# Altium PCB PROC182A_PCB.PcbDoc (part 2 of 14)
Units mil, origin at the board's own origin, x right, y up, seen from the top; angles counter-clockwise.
Board outline 3168.31 x 3700.79 mil, 8 copper layers (Top Layer, L2_GND1, L3_SIG1, L4_PWR1, L5_PWR2, L6_SIG2, L7_GND2, Bottom Layer), stack 58.1 mil thick; 580 components, 391 nets, 8314 pads, 4370 vias.
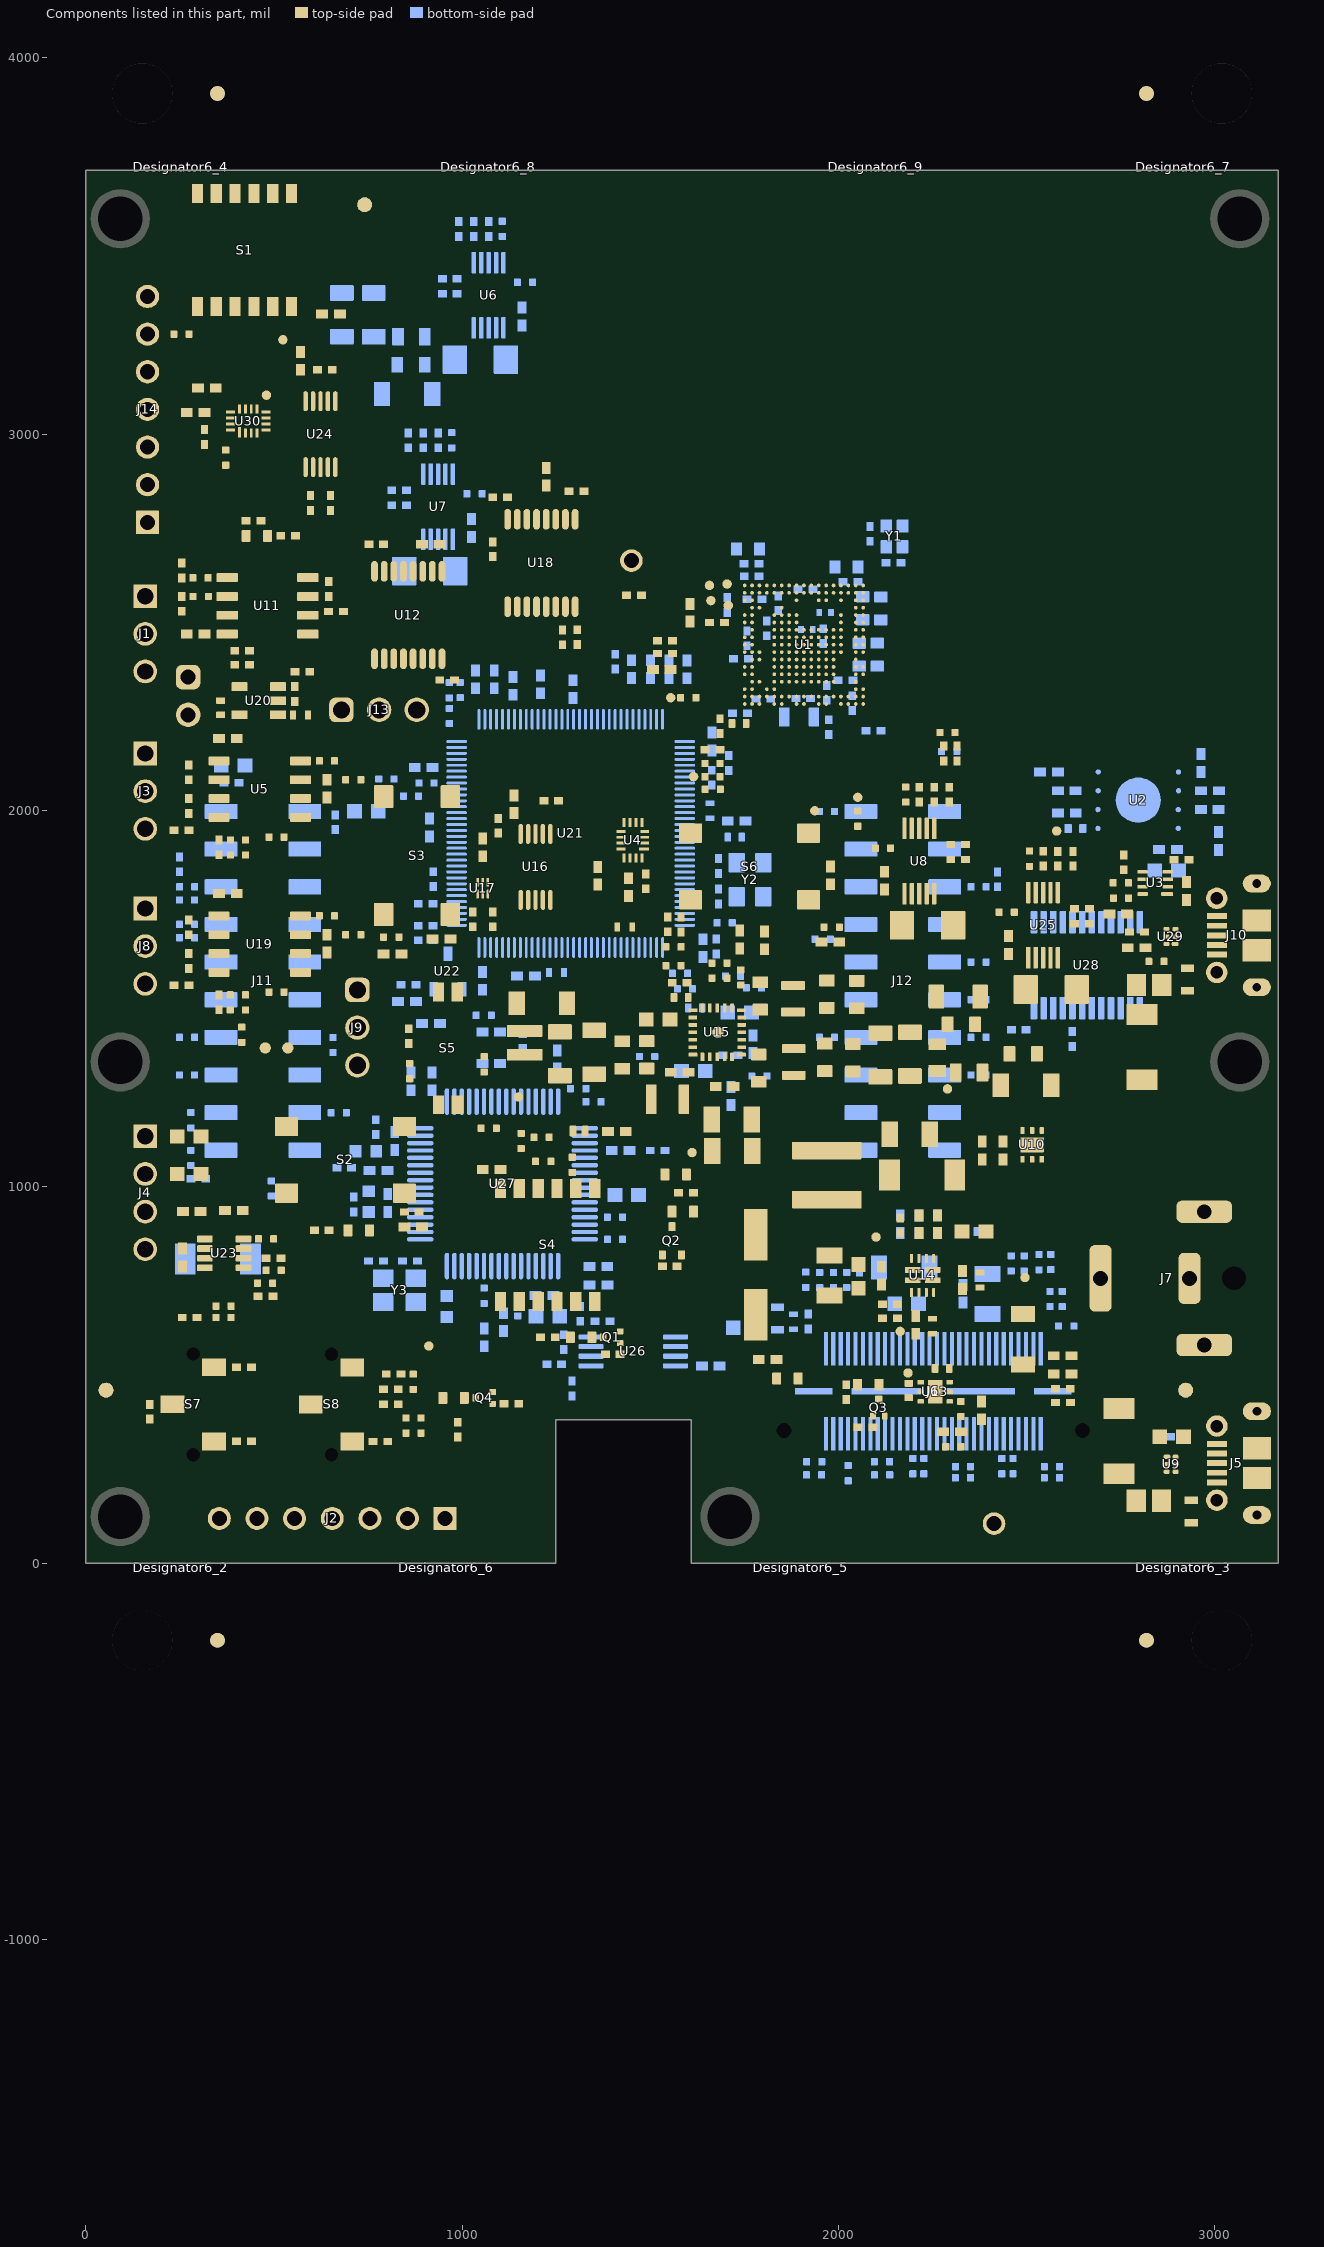
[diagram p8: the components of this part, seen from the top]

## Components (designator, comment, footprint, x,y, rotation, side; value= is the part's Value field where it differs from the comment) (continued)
R206 "CRCW040210K0FKED" 0402L 810.66,462.39 r180 top value=10.0k
R207 "CRCW04027K87FKED" 0402L 818.05,503.14 r0 top value=7.87k
R208 "CRCW040282K5FKED" 0402L 782.82,323.68 r180 top value=82.5k
R209 "CRCW040233R2FKED" 0402 1077.44,1411.22 r0 bottom value=33.2
R210 "ERJ-2GE0R00X" FP-ERJ-2GE0R00X_0402-MFG 269.38,1397.45 r0 bottom value=0
R211 "ERJ-2GE0R00X" FP-ERJ-2GE0R00X_0402-MFG 657,1377.27 r270 bottom value=0
R212 "ERJ-2GE0R00X" FP-ERJ-2GE0R00X_0402-MFG 1969.38,1397.45 r0 bottom value=0
R213 "CRCW0402220RJNED" 0402 945.08,1658.85 r180 top value=220
R214 "ERJ-2GE0R00X" FP-ERJ-2GE0R00X_0402-MFG 811.71,1663.85 r0 top value=0
R215 "CRCW0402100KFKED" 0402 815.16,1618.85 r0 top value=100k
R216 "ERJ-2GE0R00X" FP-ERJ-2GE0R00X_0402-MFG 1308.48,1261.32 r0 bottom value=0
R217 "ERJ-2GE0R00X" FP-ERJ-2GE0R00X_0402-MFG 1348.83,1226.32 r180 bottom value=0
R218 "CRCW040210K0FKED" 0402L 686.9,1050.68 r0 bottom value=10.0k
R219 "ERJ-2GE0R00X" FP-ERJ-2GE0R00X_0402-MFG 2197.61,258.24 r270 bottom value=0
R220 "ERJ-2GE0R00X" FP-ERJ-2GE0R00X_0402-MFG 2226.8,258.24 r270 bottom value=0
R221 "ERJ-2GE0R00X" FP-ERJ-2GE0R00X_0402-MFG 2372.18,1397.45 r0 bottom value=0
R222 "ERJ-2GE0R00X" FP-ERJ-2GE0R00X_0402-MFG 269.38,1297.45 r0 bottom value=0
R223 "ERJ-2GE0R00X" FP-ERJ-2GE0R00X_0402-MFG 2372.18,1297.45 r0 bottom value=0
R224 "ERJ-2GE0R00X" FP-ERJ-2GE0R00X_0402-MFG 279.56,1177.27 r90 bottom value=0
R225 "ERJ-2GE0R00X" FP-ERJ-2GE0R00X_0402-MFG 2330.57,257.17 r180 bottom value=0
R226 "ERJ-2GE0R00X" FP-ERJ-2GE0R00X_0402-MFG 2330.57,227.48 r180 bottom value=0
R227 "ERJ-2GE0R00X" FP-ERJ-2GE0R00X_0402-MFG 2433.83,258.24 r270 bottom value=0
R228 "ERJ-2GE0R00X" FP-ERJ-2GE0R00X_0402-MFG 2463.51,258.24 r270 bottom value=0
R229 "ERJ-2GE0R00X" FP-ERJ-2GE0R00X_0402-MFG 2566.78,227.48 r0 bottom value=0
R230 "ERJ-2GE0R00X" FP-ERJ-2GE0R00X_0402-MFG 2566.78,257.17 r0 bottom value=0
R231 "CRCW040210K0FKED" 0402L 1663.56,2087.29 r90 bottom value=10.0k
R232 "ERJ-2GE0R00X" FP-ERJ-2GE0R00X_0402-MFG 672.18,1197.45 r0 bottom value=0
R233 "ERJ-2RKF1001X" 0402 1054.11,1547.47 r270 bottom value=1.00k
R234 "CRCW04024K87FKED" 0402L 1406.98,2395.63 r270 bottom value=4.87k
R235 "ERJ-2GE0R00X" FP-ERJ-2GE0R00X_0402-MFG 366.12,683.31 r0 top value=0
R236 "CRCW0402330KFKED" 0402L 903.11,1752.47 r180 bottom value=330k
R237 "ERJ-2RKF1001X" 0402 919.5,1280.46 r270 bottom value=1.00k
R238 "ERJ-2GE0R00X" FP-ERJ-2GE0R00X_0402-MFG 279.56,1077.27 r90 bottom value=0
R239 "CRCW0402330KFKED" 0402L 903.11,1655.47 r0 bottom value=330k
R240 "ERJ-2GE0R00X" FP-ERJ-2GE0R00X_0402-MFG 493.41,996.12 r270 bottom value=0
R241 "ERJ-2GE0R00X" FP-ERJ-2GE0R00X_0402-MFG 2325.17,409.98 r90 top value=0
R242 "ERJ-2GE0R00X" FP-ERJ-2GE0R00X_0402-MFG 1058.37,710.97 r270 bottom value=0
R243 "ERJ-2GE0R00X" FP-ERJ-2GE0R00X_0402-MFG 1406.06,919.71 r0 bottom value=0
R244 "ERJ-2GE0R00X" FP-ERJ-2GE0R00X_0402-MFG 870.97,346.19 r0 top value=0
R245 "ERJ-2GE0R00X" FP-ERJ-2GE0R00X_0402-MFG 1561.37,1638.18 r0 top value=0
R246 "CRCW0402100KFKED" 0402L 2092.95,2211.9 r180 bottom value=100k
R247 "CRCW040210K0FKED" 0402L 1685.11,2224.26 r270 top value=10.0k
R248 "CRCW040233R2FKED" 0402 1109.7,641.03 r270 bottom locked value=33.2
R249 "CRCW040233R2FKED" 0402 1058.84,600.34 r270 bottom value=33.2
R250 "CRCW040210K0FKED" 0402L 1539.24,2417.29 r180 top value=10.0k
R251 "CRCW040233R2FKED" 0402 1421.32,1096.88 r0 bottom value=33.2
R252 "ERJ-2GEJ511X" 0402L 1519.6,1096.88 r0 bottom value=510
R253 "CRCW040210K0FKED" 0402L 635.36,3171.01 r180 top value=10.0k
R254 "ERJ-2GE0R00X" FP-ERJ-2GE0R00X_0402-MFG 414.56,1404.55 r90 top value=0
R255 "CRCW0402100KFKED" 0402L 1456.51,2572.49 r0 top value=100k
R256 "CRCW0402100KFKED" 0402L 1081.26,2694.18 r270 top value=100k
R257 "ERJ-2GE0R00X" FP-ERJ-2GE0R00X_0402-MFG 2051.07,1978.47 r90 top value=0
R258 "ERJ-2GEJ511X" 0402L 2020.2,454.73 r270 top value=510
R259 "ERJ-2GE0R00X" FP-ERJ-2GE0R00X_0402-MFG 2844.42,1599.14 r0 top value=0
R260 "CRCW040230K0FKED" 0402L 2792.79,1677.42 r0 top value=30.0k
R261 "CRCW040210K0FKED" 0402L 2279.02,2151.58 r90 top value=10.0k
R262 "CRCW0402220RJNED" 0402 1979.05,1827.93 r270 top value=220
R263 "ERJ-2GEJ511X" 0402L 2071.68,361.35 r180 top value=510
R264 "ERJ-2GE0R00X" FP-ERJ-2GE0R00X_0402-MFG 1981.92,1690.47 r180 top value=0
R265 "CRCW0402100KFKED" 0402 1978.48,1650.47 r180 top value=100k
R267 "ERJ-2GE0R00X" FP-ERJ-2GE0R00X_0402-MFG 1665.13,2090.04 r180 top value=0
R268 "ERJ-2GE0R00X" FP-ERJ-2GE0R00X_0402-MFG 1665.13,2125.04 r180 top value=0
R269 "ERJ-2GE0R00X" FP-ERJ-2GE0R00X_0402-MFG 1600.94,2299.95 r0 top value=0
R270 "ERJ-2GE0R00X" FP-ERJ-2GE0R00X_0402-MFG 1665.95,2056.5 r180 top value=0
R271 "CRCW040210K0FKED" 0402L 315.66,2992.42 r90 top value=10.0k
R272 "RC0402FR-074K7L" 0402 321.95,3122.76 r0 top value=4.70k
R273 "ERJ-2GE0R00X" FP-ERJ-2GE0R00X_0402-MFG 404.36,1921.85 r180 top value=0
R274 "CRCW0402100KFKED" 0402L 597.17,2816.9 r270 top value=100k
R275 "CRCW0402100KFKED" 0402L 650.21,2816.9 r270 top value=100k
R276 "CRCW040210K0FKED" 0402L 2314.66,2151.58 r270 top value=10.0k
R277 "ERJ-2RKF1001X" 0402 651.74,3319.65 r0 top value=1.00k
R278 "ERJ-2GE0R00X" FP-ERJ-2GE0R00X_0402-MFG 1683.76,1554.82 r180 top value=0
R279 "ERJ-2GE0R00X" FP-ERJ-2GE0R00X_0402-MFG 1578.88,1567.54 r180 bottom value=0
R280 "ERJ-2GE0R00X" FP-ERJ-2GE0R00X_0402-MFG 1491.57,1346.5 r180 bottom value=0
R281 "ERJ-2GE0R00X" FP-ERJ-2GE0R00X_0402-MFG 1775.2,1529 r0 bottom value=0
R282 "ERJ-2GE0R00X" FP-ERJ-2GE0R00X_0402-MFG 1789.71,1294.91 r0 bottom value=0
R283 "CRCW040210K0FKED" 0402L 2911.37,1869.68 r180 top value=10.0k
R284 "ERJ-2GE0R00X" FP-ERJ-2GE0R00X_0402-MFG 2293.97,2157 r180 bottom value=0
R285 "ERJ-2GE0R00X" FP-ERJ-2GE0R00X_0402-MFG 371.87,2937.61 r90 top value=0
R286 "ERJ-2GE0R00X" FP-ERJ-2GE0R00X_0402-MFG 254.35,3265.75 r0 top value=0
R287 "ERJ-2GEJ511X" 0402L 627.15,884.63 r180 top value=510
R288 "CRCW040210K0FKED" 0402L 1713.27,1349.74 r180 bottom value=10.0k
R289 "CRCW040219K1FKED" 0402 1773.2,1379.21 r270 bottom value=19.1k
R290 "ERJ-2GE0R00X" FP-ERJ-2GE0R00X_0402-MFG 864.1,2038.44 r0 bottom value=0
S1 "218-6LPST" SW_218-6LPST 421.89,3489.18 r270 top
S2 "PTS645SM43SMTR92 LFS" SW_PTS645SM43SMT 690.06,1072.19 r0 top
S3 "PTS645SM43SMTR92 LFS" SW_PTS645SM43SMT 880.12,1880.34 r270 top
S4 "218-6LPST" SW_218-6LPST 1227.05,846.11 r90 top
S5 "218-2LPST" SW_218-2LP 962.08,1368.36 r270 top
S6 "PTS645SM43SMTR92 LFS" SW_PTS645SM43SMT 1763.78,1851.38 r0 top
S7 "CL-SB-12A-01T" SW_CL-SB-12A-01 285.57,422.47 r180 top
S8 "CL-SB-12A-01T" SW_CL-SB-12A-01 653.02,422.1 r180 top
TP1 "TESTPOINT" TP_25MIL-SMT 911.49,577.38 r270 top
TP2 "TESTPOINT" TP_25MIL-SMT 1936.9,1999.44 r90 top
TP3 "TESTPOINT" TP_25MIL-SMT 2051.07,2035.16 r90 top
TP4 "TESTPOINT" TP_25MIL-SMT 480.15,3103.58 r180 top
TP5 "TESTPOINT" TP_25MIL-SMT 1703.94,2601.77 r90 top
TP6 "TESTPOINT" TP_25MIL-SMT 1657,2598.24 r90 top
TP7 "TESTPOINT" TP_25MIL-SMT 2099.69,866.91 r90 top
TP8 "TESTPOINT" TP_25MIL-SMT 1614.95,2090.04 r90 top
TP9 "TESTPOINT" TP_25MIL-SMT 1554.15,2299.79 r90 top
TP11 "TESTPOINT" TP_25MIL-SMT 1707.08,2545.15 r90 top
TP12 "TESTPOINT" TP_25MIL-SMT 1660.83,2557.74 r90 top
TP13 "TESTPOINT" TP_25MIL-SMT 2163.76,616.28 r90 top
TP14 "TESTPOINT" TP_25MIL-SMT 2495.27,759.44 r90 top
TP15 "TESTPOINT" TP_25MIL-SMT 1610.86,1091.39 r90 top
TP16 "TESTPOINT" TP_25MIL-SMT 1149.56,1239.15 r270 top
TP17 "TESTPOINT" TP_25MIL-SMT 2579.58,1945.65 r90 top
TP18 "TESTPOINT" TP_25MIL-SMT 523.76,3250.69 r90 top
TP19 "TESTPOINT" TP_25MIL-SMT 2289.48,1260.55 r90 top
TP20 "TESTPOINT" TP_25MIL-SMT 2184.58,505.88 r90 top
TP21 "TESTPOINT" TP_VIA_060RND040 2413.15,105.66 r90 top
TP22 "TESTPOINT" TP_VIA_060RND040 1449.62,2663.99 r90 top
U1 "AWRL68442LQGAMF" 0-MFG 1908.07,2440.64 r270 top locked
U2 "MX25V1635FZNQ03" FP-MX25V1635FZNQ03_WSON8-MFG 2796.23,2027.59 r0 bottom
U3 "TMP451AQDQFRQ1" DQF0008A 2841.43,1807.7 r180 top
U4 "TS3A5018RSVR" RSV0016A 1453.74,1921.26 r180 top
U5 "TCAN3403DRQ1" D0008B-MFG 462.45,2056.85 r180 top
U6 "INA228AIDGST" DGS0010A-MFG 1070.46,3368.94 r270 bottom
U7 "INA228AIDGST" DGS0010A-MFG 936.06,2807.15 r270 bottom
U8 "INA228AIDGST" DGS0010A-MFG 2214.6,1865.88 r270 top
U9 "TPD4E004DRYR" DRY0006A 2883.52,263.22 r0 top
U10 "TVS1800DRVR" DRV0006A 2514.32,1111.65 r270 top
U11 "CAT24C08WI-GT3" SOIC-8 482.9,2543.79 r180 top
U12 "TS3A44159PWR" PW0016A_N 856.89,2519.38 r90 top
U13 "TLV75533PDRVR" DRV0006A 2256.79,455.74 r0 top
U14 "TPS2121RUXR" RUX0012A 2223.33,765.07 r180 top
U15 "TPS65036501RAYRQ1" RAY0024B-MFG 1677.79,1410.77 r0 top locked
U16 "TS3A24157DGSR" DGS0010A_N 1194.96,1850.25 r90 top
U17 "SN74LVC1G11DSFR" DSF0006A 1054.8,1793.8 r90 top
U18 "TS3A44159PWR" PW0016A_N 1210.47,2657.7 r90 top
U19 "TCAN3403DRQ1" D0008B-MFG 462.28,1645.14 r180 top
U20 "TPS78417QDBVRQ1" DBV0005A-MFG 459.49,2291.81 r180 top
U21 "TM4C1294NCPDTT3" PDT0128A 1288.51,1939.32 r0 bottom locked
U22 "LM4040C25QDBZR" DBZ0003A_N 962.11,1572.47 r90 bottom
U23 "TLIN1039DDFRQ1" DDF0008A-MFG 367.95,823.53 r180 top
U24 "TS3A24157DGSR" DGS0010A_N 623.69,2999.86 r90 top
U25 "INA228AIDGST" DGS0010A-MFG 2543.46,1695.64 r270 top
U26 "93LC46B-I/ST" TSSOP-8 1454.71,563.12 r0 bottom
U27 "FT4232HL" LQFP64_N 1107.38,1008.3 r0 bottom locked
U28 "TS3A27518EPWR" PW0024A-MFG 2659.93,1589.22 r270 bottom
U29 "TPD4E004DRYR" DRY0006A 2883.23,1665.25 r180 top
U30 "TS3A5018RSVR" RSV0016A 431.86,3034.84 r90 top
Y1 "FW4000044Q" FP-FW4000044Q_4-SMD-2.0x1.6mm-MFG 2148.39,2728.24 r90 bottom
Y2 "ECS-160-8-33Q-RES-TR" FP-ECS-160-8-33Q-RES-TR_SMT4_3MM2_2MM5-MFG 1764.81,1816.36 r270 bottom
Y3 "NX3225SA-12.000M-STD-CRS-2" NDK_NX3225SA 833.8,725.83 r90 bottom
ZZ1 "This Assembly Note is for PCB labels only" AssemblyNoteLabel -334.65,4627.95 r0 top
ZZ2 "These assemblies are ESD sensitive, ESD precautions shall be observed." AssemblyNote -337.73,4557.31 r0 top
ZZ3 "These assemblies must be clean and free from flux and all contaminants. Use of no clean flux is not acceptable." AssemblyNote -336.61,4494.1 r0 top
ZZ4 "These assemblies must comply with workmanship standards IPC-A-610 Class 2, unless otherwise specified." AssemblyNote -336.61,4444.88 r0 top
ZZ5 "INDICATION FOR COMPONENTS D* ARE GIVEN AT THEIR CATHODE SIDE." AssemblyNote -336.61,4382.88 r0 top

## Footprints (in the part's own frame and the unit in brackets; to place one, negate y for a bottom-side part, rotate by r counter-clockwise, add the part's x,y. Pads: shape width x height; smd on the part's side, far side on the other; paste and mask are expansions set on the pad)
0-MFG [mm]
  round 0.25 smd paste+0 mask+0.05: A1(-4,4) A2(-3.5,4) A3(-3,4) A4(-2.5,4) A5(-2,4) A6(-1.5,4) A7(-1,4) A8(-0.5,4) A9(0,4) A10(0.5,4) A12(1.5,4) A13(2,4) A15(3,4) A16(3.5,4) A17(4,4) B1(-4,3.5) B2(-3.5,3.5) B3(-3,3.5) B4(-2.5,3.5) B5(-2,3.5) B6(-1.5,3.5) B7(-1,3.5) B8(-0.5,3.5) B9(0,3.5) B10(0.5,3.5) B11(1,3.5) B12(1.5,3.5) B13(2,3.5) B14(2.5,3.5) B15(3,3.5) B16(3.5,3.5) B17(4,3.5) C1(-4,3) C2(-3.5,3) C16(3.5,3) C17(4,3) D1(-4,2.5) D2(-3.5,2.5) D3(-3,2.5) D5(-2,2.5) D6(-1.5,2.5) D7(-1,2.5) D8(-0.5,2.5) D9(0,2.5) D10(0.5,2.5) D16(3.5,2.5) D17(4,2.5) E1(-4,2) E2(-3.5,2) E7(-1,2) E8(-0.5,2) E9(0,2) E10(0.5,2) E11(1,2) E12(1.5,2) E13(2,2) E14(2.5,2) E16(3.5,2) F1(-4,1.5) F2(-3.5,1.5) F3(-3,1.5) F7(-1,1.5) F8(-0.5,1.5) F9(0,1.5) F10(0.5,1.5) F11(1,1.5) F12(1.5,1.5) F13(2,1.5) F14(2.5,1.5) F16(3.5,1.5) F17(4,1.5) G1(-4,1) G2(-3.5,1) G3(-3,1) G7(-1,1) G8(-0.5,1) G9(0,1) G10(0.5,1) G11(1,1) G12(1.5,1) G13(2,1) G14(2.5,1) G16(3.5,1) G17(4,1) H1(-4,0.5) H2(-3.5,0.5) H7(-1,0.5) H8(-0.5,0.5) H9(0,0.5) H10(0.5,0.5) H11(1,0.5) H12(1.5,0.5) H13(2,0.5) H14(2.5,0.5) H16(3.5,0.5) J1(-4,0) J2(-3.5,0) J7(-1,0) J8(-0.5,0) J9(0,0) J10(0.5,0) J11(1,0) J12(1.5,0) J13(2,0) J14(2.5,0) J16(3.5,0) J17(4,0) K1(-4,-0.5) K2(-3.5,-0.5) K3(-3,-0.5) K5(-2,-0.5) K6(-1.5,-0.5) K7(-1,-0.5) K8(-0.5,-0.5) K9(0,-0.5) K10(0.5,-0.5) K11(1,-0.5) K12(1.5,-0.5) K13(2,-0.5) K14(2.5,-0.5) K16(3.5,-0.5) K17(4,-0.5) L1(-4,-1) L2(-3.5,-1) L5(-2,-1) L6(-1.5,-1) L7(-1,-1) L8(-0.5,-1) L9(0,-1) L10(0.5,-1) L11(1,-1) L12(1.5,-1) L13(2,-1) L14(2.5,-1) L16(3.5,-1) M1(-4,-1.5) M2(-3.5,-1.5) M4(-2.5,-1.5) M5(-2,-1.5) M6(-1.5,-1.5) M7(-1,-1.5) M8(-0.5,-1.5) M9(0,-1.5) M10(0.5,-1.5) M11(1,-1.5) M12(1.5,-1.5) M13(2,-1.5) M14(2.5,-1.5) M16(3.5,-1.5) M17(4,-1.5) N1(-4,-2) N2(-3.5,-2) N5(-2,-2) N6(-1.5,-2) N7(-1,-2) N8(-0.5,-2) N9(0,-2) N10(0.5,-2) N11(1,-2) N12(1.5,-2) N13(2,-2) N14(2.5,-2) N15(3,-2) N16(3.5,-2) N17(4,-2) P1(-4,-2.5) P2(-3.5,-2.5) P15(3,-2.5) P16(3.5,-2.5) R1(-4,-3) R2(-3.5,-3) R4(-2.5,-3) R10(0.5,-3) R11(1,-3) R14(2.5,-3) R16(3.5,-3) R17(4,-3) T1(-4,-3.5) T2(-3.5,-3.5) T3(-3,-3.5) T4(-2.5,-3.5) T5(-2,-3.5) T6(-1.5,-3.5) T7(-1,-3.5) T8(-0.5,-3.5) T9(0,-3.5) T10(0.5,-3.5) T11(1,-3.5) T12(1.5,-3.5) T13(2,-3.5) T14(2.5,-3.5) T15(3,-3.5) T16(3.5,-3.5) T17(4,-3.5) U1(-4,-4) U2(-3.5,-4) U3(-3,-4) U5(-2,-4) U6(-1.5,-4) U8(-0.5,-4) U9(0,-4) U10(0.5,-4) U12(1.5,-4) U13(2,-4) U15(3,-4) U16(3.5,-4) U17(4,-4)
  silkscreen extent -5.12,-4.55 4.55,4.55, body extent -5.05,-5.05 5.05,5.05, height 0.25
0402 [mm] "0402 from SM-752 data"
  rect 0.8x0.6 smd: 1(-0.6,0) 2(0.6,0)
  silkscreen extent -1.22,-0.52 1.22,0.52, body extent -0.55,-0.3 0.55,0.3, height 0.6
0402_070 [mil] "SMD, 2-Leads, Body 1.2x0.7mm, Height 0.7mm"
  rect 15x24 smd: 1(-20,0) 2(20,0)
  body extent -24,-14 24,14, height 28
0402L [mm] "0402 from SM-752 data"
  rect 0.6x0.5 smd: 1(-0.5,0) 2(0.5,0)
  body extent -0.55,-0.3 0.55,0.3, height 0.6
0603 [mm] "0603 from SM-752 data"
  rect 1x0.95 smd: 1(-0.8,0) 2(0.8,0)
  silkscreen extent -1.52,-0.69 1.52,0.69, body extent -0.87,-0.47 0.87,0.47, height 1
0603L [mm] "0603 from SM-752 data"
  rect 0.8x0.85 smd: 1(-0.7,0) 2(0.7,0)
  silkscreen extent -0.07,-0.33 0.07,0.33, body extent -0.87,-0.47 0.87,0.47, height 1
0603S [mil]
  rect 20x35 smd: 1(-30,0) 2(30,0)
  body extent -34,-19 34,19, height 39
0805 [mm] "0805 from SM-752 data"
  rect 1.3x1.5 smd: 1(-0.85,0) 2(0.85,0)
  silkscreen extent -1.72,-0.97 1.72,0.97, body extent -1.1,-0.72 1.1,0.72, height 1.45
1206_180 [mm] "1206_180"
  rect 1.1x1.6 smd: 1(-1.7,0) 2(1.7,0)
  silkscreen extent -0.9,-1 0.9,1, body extent -1.75,-0.95 1.75,0.95, height 1.8
1206_180L [mm] "1206_180"
  rect 1.1x1.75 smd: 1(-1.35,0) 2(1.35,0)
  silkscreen extent -0.4,-0.77 0.4,0.77, body extent -1.75,-0.95 1.75,0.95, height 1.8
AssemblyNote [mil] "Assembly Note"
AssemblyNoteLabel [mil] "Assembly Note for PCB Labels"
BRAKE_WAY_HOLES1X3_CUST [mm]
  round 0.373 hole 0.5 unplated mask+0.152: ""(-0.838,0.746) ""(0,0.746) ""(0.838,0.746)
CE_Mark_5mm [mil] "Minimum text height for CE Mark"
  silkscreen extent -138,-98 138,98
CONN_105017-0001 [mm] "Molex Micro USB-B"
  rect 0.4x1.35 smd: 1(-1.3,1.35) 2(-0.65,1.35) 3(0,1.35) 4(0.65,1.35) 5(1.3,1.35)
  oval 1.2x1.9 hole 0.6 slot 1.3 at 90 deg: 6(-3.5,-1.35) 9(3.5,-1.35)
  rect 1.5x1.9 smd: 7(-1,-1.35) 8(1,-1.35)
  round 1.45 hole 0.85: 10(2.5,1.35) 11(-2.5,1.35)
  Top Layer region: -3.499,-2.301 -2.299,-2.301 -2.299,-0.401 -3.499,-0.401
  Top Layer region: 3.501,-0.401 2.301,-0.401 2.301,-2.301 3.501,-2.301
  silkscreen extent -4.1,-0.2 4.1,1.4, body extent -4.1,-3.93 4.1,1.5, height 2.72
CUI_PJ-063AH [mm] "DC POWER JACK, R/A, TH"
  rrect50% 1.5x4.5 hole 1 square: 1(-4.5,0)
  rrect50% 1.5x3.45 hole 1 square: 2(1.5,0)
  oval 1.35x1.3 hole 1.6 unplated mask+0.102: ALIGN(4.5,0)
  rrect50% 3.75x1.5 hole 1 square: S1(2.5,-4.5) S2(2.5,4.5)
  body extent -5.5,-5.15 7.5,5.15, height 9
D0008B-MFG [mm]
  rrect17% 1.4x0.6 smd paste+0 mask+0: 1(-2.75,1.905) 2(-2.75,0.635) 3(-2.75,-0.635) 4(-2.75,-1.905) 5(2.75,-1.905) 6(2.75,-0.635) 7(2.75,0.635) 8(2.75,1.905)
  silkscreen extent -4.14,-2.5 1.5,2.5, body extent -3,-2.45 3,2.45, height 1.75
DBV0005A-MFG [mm]
  rrect17% 1.1x0.6 smd paste+0 mask+0: 1(-1.3,0.95) 2(-1.3,0) 3(-1.3,-0.95) 4(1.3,-0.95) 5(1.3,0.95)
  silkscreen extent -1.4,-1.53 0.87,1.86, body extent -1.95,-1.78 1.95,1.78, height 0.25
DBZ0003A_N [mm] "SOT23, 3-Leads, Body 2.9x1.3mm, Pitch 0.95mm, Lead Span 2.4mm, IPC Medium Density"
  rrect17% 1x0.6 smd: 1(-1.2,0.95) 2(-1.2,-0.95) 3(1.2,0)
  silkscreen extent 0.2,-1.5 0.7,1.5, body extent -1.26,-1.46 1.26,1.46, height 0.98
DDF0008A-MFG [mm]
  rrect22% 1.05x0.45 smd paste+0 mask+0: 1(-1.3,0.975) 2(-1.3,0.325) 3(-1.3,-0.325) 4(-1.3,-0.975) 5(1.3,-0.975) 6(1.3,-0.325) 7(1.3,0.325) 8(1.3,0.975)
  silkscreen extent -2.38,-1.47 0.4,1.48, body extent -1.92,-1.72 1.92,1.73, height 0.25
DGS0010A-MFG [mm]
  rrect33% 1.45x0.3 smd paste+0 mask+0: 1(-2.2,1) 2(-2.2,0.5) 3(-2.2,0) 4(-2.2,-0.5) 5(-2.2,-1) 6(2.2,-1) 7(2.2,-0.5) 8(2.2,0) 9(2.2,0.5) 10(2.2,1)
  silkscreen extent -3.41,-1.55 1.05,1.55, body extent -2.45,-1.5 2.45,1.5, height 1.1
DGS0010A_N [mm] "TSSOP, 10-Leads, Body 3x3mm, Pitch 0.5mm, IPC Medium Density"
  oval 1.35x0.3 smd: 1(-2.225,1) 2(-2.225,0.5) 3(-2.225,0) 4(-2.225,-0.5) 5(-2.225,-1) 6(2.225,-1) 7(2.225,-0.5) 8(2.225,0) 9(2.225,0.5) 10(2.225,1)
  silkscreen extent -2.75,-1.55 0.9,1.55, body extent -2.45,-1.5 2.45,1.5, height 0.96
DQF0008A [mm] "SON-8"
  rrect40% 0.8x0.25 smd: 1(-0.8,0.75)
  rrect40% 0.7x0.25 smd: 2(-0.85,0.25) 3(-0.85,-0.25) 4(-0.85,-0.75) 5(0.85,-0.75) 6(0.85,-0.25) 7(0.85,0.25) 8(0.85,0.75)
  silkscreen extent -1.15,-1.17 0.38,1.17, body extent -1.05,-1.05 1.05,1.05, height 0.81
DRV0006A [mm] "SON, 6-Leads, Body 2x2mm, Pitch 0.65mm, Thermal Pad 1.6x1mm, TI Recommended"
  rrect33% 0.45x0.3 smd: 1(-0.975,0.65) 2(-0.975,0) 3(-0.975,-0.65) 4(0.975,-0.65) 5(0.975,0) 6(0.975,0.65)
  rrect14% 1x0.7 on Top Paste: 7(0,0.45) 7(0,-0.45)
  rrect10% 1x1.6 smd paste-0.5: 7(0,0)
  silkscreen extent -1.05,-1.2 1.05,1.2, body extent -1.05,-1.05 1.05,1.05, height 0.81
DRY0006A [mm] "USON-6"
  rrect67% 0.45x0.3 smd paste-0.05 mask-0.05: 1(-0.275,0.5)
  rrect67% 0.4x0.3 smd paste-0.05 mask-0.05: 2(-0.3,0) 3(-0.3,-0.5) 4(0.3,-0.5) 5(0.3,0) 6(0.3,0.5)
  body extent -0.5,-0.72 0.5,0.73, height 0.58
DSF0006A [mm] "TI recommended land pattern"
  rrect59% 0.6x0.17 smd mask+0.045: 1(-0.4,0.35) 2(-0.4,0) 3(-0.4,-0.35) 4(0.4,-0.35) 5(0.4,0) 6(0.4,0.35)
  silkscreen extent -0.6,-0.63 0.6,0.63, body extent -0.5,-0.5 0.5,0.5, height 0.48
FIDUCIAL10-20 [mm]
  round 1 smd mask+0.5: 1(0,0)
  Top Layer keep-out circle w1.178: c0,0 r0.5
FP-0022288072_HDR7-MFG [mm]
  rrect6% 1.57x1.57 hole 1.02 paste-2539.97 mask+0: 1(-7.62,-2.925)
  round 1.57 hole 1.02 paste-2539.97 mask+0: 2(-5.08,-2.925) 3(-2.54,-2.925) 4(0,-2.925) 5(2.54,-2.925) 6(5.08,-2.925) 7(7.62,-2.925)
  silkscreen extent -9.11,-3.05 9.01,1.27, body extent -9.11,-3.81 9.12,7.95, height 0.25
FP-CGA4J3X7S1A106K125AE_0805-MFG [mm]
  rrect13% 0.8x1.05 smd paste+0 mask+0: 1(-0.925,0) 2(0.925,0)
  silkscreen extent -0.15,-0.75 0.15,0.75, body extent -1.2,-0.62 1.2,0.63, height 1.5
FP-ECS-160-8-33Q-RES-TR_SMT4_3MM2_2MM5-MFG [mm]
  rrect9% 1.3x1.1 smd paste+0 mask+0: 1(-1.15,-0.9) 2(1.15,-0.9) 3(1.15,0.9) 4(-1.15,0.9)
  silkscreen extent -1.52,-1.96 0.13,1.3, body extent -1.6,-1.25 1.6,1.25, height 0.8
FP-ERJ-2GE0R00X_0402-MFG [mm]
  rrect21% 0.475x0.5 smd paste+0 mask+0: 1(-0.513,0) 2(0.513,0)
  silkscreen extent -0.53,-0.63 0.53,0.63, body extent -0.5,-0.25 0.5,0.25, height 0.4
FP-FW4000044Q_4-SMD-2.0x1.6mm-MFG [mm]
  rrect13% 0.9x0.8 smd paste+0 mask+0: 1(-0.7,-0.55) 2(0.7,-0.55) 3(0.7,0.55) 4(-0.7,0.55)
  silkscreen extent -1.4,-1.1 1.01,1.13, body extent -1,-0.8 1,0.8, height 0.55
FP-GCJ21BR71C475KA01L_0805-MFG [mm]
  rrect14% 0.7x1.3 smd paste+0 mask+0: 1(-1,0) 2(1,0)
  silkscreen extent -0.28,-0.73 0.28,0.73, body extent -1,-0.63 1,0.63, height 1.45
FP-GCM188D70E226ME36D_0603-MFG [mm]
  rrect13% 0.75x0.9 smd paste+0 mask+0: 1(-0.775,0) 2(0.775,0)
  silkscreen extent -0.03,-0.5 0.03,0.5, body extent -0.8,-0.4 0.8,0.4, height 1
FP-GCM188D70J106ME36D_0603-MFG [mm]
  rrect13% 0.75x0.9 smd paste+0 mask+0: 1(-0.775,0) 2(0.775,0)
  body extent -0.8,-0.4 0.8,0.4, height 1
FP-GRM31CR70J226ME19K_1206-MFG [mm]
  rrect10% 1.05x1.6 smd paste+0 mask+0: 1(-1.475,0) 2(1.475,0)
  silkscreen extent -0.58,-0.9 0.58,0.9, body extent -2.1,-1 2.1,1, height 0.25
FP-GRT155C71A225KE13D_0402-MFG [mm]
  rrect22% 0.45x0.6 smd paste+0 mask+0: 1(-0.475,0) 2(0.475,0)
  silkscreen extent -0.5,-0.7 0.5,-0.7, body extent -0.5,-0.25 0.5,0.25, height 0.7
FP-GRT155R70J105KE01D_0402-MFG [mm]
  rrect25% 0.4x0.5 smd paste+0 mask+0: 1(-0.4,0) 2(0.4,0)
  silkscreen extent -0.53,-0.63 0.53,0.63, body extent -0.5,-0.25 0.5,0.25, height 0.55
"FP-LQM2MPZR10MJHL_0806 (2016)-MFG" [mm]
  rrect13% 0.8x2.4 smd paste-1000 mask-1000: 1(-0.8,0) 2(0.8,0)
  silkscreen extent -1.1,-1.5 1.1,1.5, body extent -1.3,-1.3 1.3,1.3, height 0.25
FP-MPZ2012S300ATD25_0805-MFG [mm]
  rrect13% 0.8x1.2 smd paste+0 mask+0: 1(-0.9,0) 2(0.9,0)
  silkscreen extent -0.13,-0.72 0.13,0.72, body extent -1,-0.63 1,0.63, height 1.05
FP-MX25V1635FZNQ03_WSON8-MFG [mm]
  round 0.36 smd paste+0 mask+0: 1(-2.72,1.905) 2(-2.72,0.635) 3(-2.7,-0.635) 4(-2.7,-1.905) 5(2.72,-1.905) 6(2.72,-0.635) 7(2.7,0.635) 8(2.7,1.905)
  round 3.06 smd paste+0 mask+0: 9(0,0)
  Top Layer region: 3,1.705 2.6,1.705 2.523,1.72 2.459,1.764 2.415,1.828 2.4,1.905 2.4,1.905 2.415,1.982 2.459,2.046 2.523,2.09 2.6,2.105 2.6,2.105 3,2.105
  Top Layer region: 3,0.435 2.6,0.435 2.523,0.45 2.459,0.494 2.415,0.558 2.4,0.635 2.4,0.635 2.415,0.712 2.459,0.776 2.523,0.82 2.6,0.835 2.6,0.835 3,0.835
  Top Layer region: 3,-0.835 2.6,-0.835 2.523,-0.82 2.459,-0.776 2.415,-0.712 2.4,-0.635 2.4,-0.635 2.415,-0.558 2.459,-0.494 2.523,-0.45 2.6,-0.435 2.6,-0.435 3,-0.435
  Top Layer region: 3,-2.105 2.6,-2.105 2.523,-2.09 2.459,-2.046 2.415,-1.982 2.4,-1.905 2.4,-1.905 2.415,-1.828 2.459,-1.764 2.523,-1.72 2.6,-1.705 2.6,-1.705 3,-1.705
  Top Layer region: -3,-1.705 -2.6,-1.705 -2.523,-1.72 -2.459,-1.764 -2.415,-1.828 -2.4,-1.905 -2.4,-1.905 -2.427,-2.005 -2.5,-2.078 -2.6,-2.105 -2.6,-2.105 -3,-2.105
  Top Layer region: -3,-0.435 -2.6,-0.435 -2.523,-0.45 -2.459,-0.494 -2.415,-0.558 -2.4,-0.635 -2.4,-0.635 -2.427,-0.735 -2.5,-0.808 -2.6,-0.835 -2.6,-0.835 -3,-0.835
  Top Layer region: -3,0.835 -2.6,0.835 -2.523,0.82 -2.459,0.776 -2.415,0.712 -2.4,0.635 -2.4,0.635 -2.427,0.535 -2.5,0.462 -2.6,0.435 -2.6,0.435 -3,0.435
  Top Layer region: -3,2.105 -2.6,2.105 -2.523,2.09 -2.459,2.046 -2.415,1.982 -2.4,1.905 -2.4,1.905 -2.427,1.805 -2.5,1.732 -2.6,1.705 -2.6,1.705 -3,1.705
  Top Layer region: 1.7,2 1.7,-2 -1.7,-2 -1.7,1.6 -1.3,2 1.7,2
  silkscreen extent -3.05,-2.55 3.05,3.12, body extent -3,-2.49 3,2.49, height 0.8
FP-RC0402FR-1047K5L_0402-MFG [mm]
  rrect20% 0.5x0.6 smd paste+0 mask+0: 1(-0.5,0) 2(0.5,0)
  silkscreen extent -0.5,-0.52 0.5,0.67, body extent -0.5,-0.25 0.5,0.25, height 0.4
FP-SSM3K35AMFV,L3F_SOT-723-MFG [mm]
  rrect25% 0.45x0.4 smd paste+0 mask+0: 1(-0.575,0.4) 2(-0.575,-0.4)
  rrect22% 0.45x0.5 smd paste+0 mask+0: 3(0.575,0)
  silkscreen extent -0.43,-0.98 0.71,0.72, body extent -0.9,-0.73 0.9,0.73, height 0.25
FP-TFM252012ALVA1R5MTAA_1008-MFG [mm]
  rrect14% 0.7x2 smd paste+0 mask+0: 1(-1.1,0) 2(1.1,0)
  silkscreen extent -0.38,-1.1 0.38,1.1, body extent -1.55,-1.2 1.55,1.2, height 0.25
FP-TLMY1100-GS15_0603-MFG [mm]
  rrect17% 0.6x0.8 smd paste+0 mask+0: 1(-0.725,0) 2(0.725,0)
  silkscreen extent -1.61,-0.45 0.05,0.45, body extent -1.12,-0.55 1.12,0.55, height 0.25
FP-WSL1206R0100FEB_1206-MFG [mm]
  rrect6% 1.65x1.93 smd paste+0 mask+0: 1(-1.725,0) 2(1.725,0)
  silkscreen extent -0.53,-0.93 0.53,0.93, body extent -2.65,-1.06 2.65,1.06, height 0.25
FP-WSL1206R0200FEB_1206-MFG [mm]
  rrect6% 1.65x1.93 smd paste+0 mask+0: 1(-1.725,0) 2(1.725,0)
  silkscreen extent -0.53,-0.93 0.53,0.93, body extent -2.65,-1.06 2.65,1.06, height 0.25
FP-WSL1206R0400FEB_1206-MFG [mm]
  rrect6% 1.65x1.93 smd paste+0 mask+0: 1(-1.725,0) 2(1.725,0)
  silkscreen extent -0.53,-0.93 0.53,0.93, body extent -1.6,-0.8 1.6,0.8, height 0.89
FP-XGL5050-472MEC_SMT2_5MM28_5MM48-MFG [mm]
  rrect8% 1.18x4.7 smd paste+0 mask+0: 1(-1.655,0) 2(1.655,0)
  silkscreen extent -3.4,-2.84 2.74,2.84, body extent -2.84,-2.94 2.84,2.94, height 0.25
IEC_HotSurface_Small [mil]
  silkscreen extent -107,-93 107,92
LQFP64_N [mm] "Thin QFP, 64-Leads, Body 10x10mm, Pitch 0.5mm, IPC Medium Density"
  oval 1.8x0.3 smd: 1(-5.55,3.75) 2(-5.55,3.25) 3(-5.55,2.75) 4(-5.55,2.25) 5(-5.55,1.75) 6(-5.55,1.25) 7(-5.55,0.75) 8(-5.55,0.25) 9(-5.55,-0.25) 10(-5.55,-0.75) 11(-5.55,-1.25) 12(-5.55,-1.75) 13(-5.55,-2.25) 14(-5.55,-2.75) 15(-5.55,-3.25) 16(-5.55,-3.75) 33(5.55,-3.75) 34(5.55,-3.25) 35(5.55,-2.75) 36(5.55,-2.25) 37(5.55,-1.75) 38(5.55,-1.25) 39(5.55,-0.75) 40(5.55,-0.25) 41(5.55,0.25) 42(5.55,0.75) 43(5.55,1.25) 44(5.55,1.75) 45(5.55,2.25) 46(5.55,2.75) 47(5.55,3.25) 48(5.55,3.75)
  oval 0.3x1.8 smd: 17(-3.75,-5.55) 18(-3.25,-5.55) 19(-2.75,-5.55) 20(-2.25,-5.55) 21(-1.75,-5.55) 22(-1.25,-5.55) 23(-0.75,-5.55) 24(-0.25,-5.55) 25(0.25,-5.55) 26(0.75,-5.55) 27(1.25,-5.55) 28(1.75,-5.55) 29(2.25,-5.55) 30(2.75,-5.55) 31(3.25,-5.55) 32(3.75,-5.55) 49(3.75,5.55) 50(3.25,5.55) 51(2.75,5.55) 52(2.25,5.55) 53(1.75,5.55) 54(1.25,5.55) 55(0.75,5.55) 56(0.25,5.55) 57(-0.25,5.55) 58(-0.75,5.55) 59(-1.25,5.55) 60(-1.75,5.55) 61(-2.25,5.55) 62(-2.75,5.55) 63(-3.25,5.55) 64(-3.75,5.55)
  silkscreen extent -6.96,-4.25 4.25,4.25, body extent -5,-5 5,5, height 1.6
NDK_NX3225SA [mm] "NDK"
  rect 1.2x1.4 smd: 1(-0.8,1.1) 2(-0.8,-1.1) 3(0.8,-1.1) 4(0.8,1.1)
  body extent -1.3,-1.65 1.3,1.65, height 0.7
PDT0128A [mm] "Thin QFP, 128-Leads, Body 14x14mm, Pitch 0.4mm"
  oval 1.4x0.2 smd: 1(-7.7,6.2) 2(-7.7,5.8) 3(-7.7,5.4) 4(-7.7,5) 5(-7.7,4.6) 6(-7.7,4.2) 7(-7.7,3.8) 8(-7.7,3.4) 9(-7.7,3) 10(-7.7,2.6) 11(-7.7,2.2) 12(-7.7,1.8) 13(-7.7,1.4) 14(-7.7,1) 15(-7.7,0.6) 16(-7.7,0.2) 17(-7.7,-0.2) 18(-7.7,-0.6) 19(-7.7,-1) 20(-7.7,-1.4) 21(-7.7,-1.8) 22(-7.7,-2.2) 23(-7.7,-2.6) 24(-7.7,-3) 25(-7.7,-3.4) 26(-7.7,-3.8) 27(-7.7,-4.2) 28(-7.7,-4.6) 29(-7.7,-5) 30(-7.7,-5.4) 31(-7.7,-5.8) 32(-7.7,-6.2) 65(7.7,-6.2) 66(7.7,-5.8) 67(7.7,-5.4) 68(7.7,-5) 69(7.7,-4.6) 70(7.7,-4.2) 71(7.7,-3.8) 72(7.7,-3.4) 73(7.7,-3) 74(7.7,-2.6) 75(7.7,-2.2) 76(7.7,-1.8) 77(7.7,-1.4) 78(7.7,-1) 79(7.7,-0.6) 80(7.7,-0.2) 81(7.7,0.2) 82(7.7,0.6) 83(7.7,1) 84(7.7,1.4) 85(7.7,1.8) 86(7.7,2.2) 87(7.7,2.6) 88(7.7,3) 89(7.7,3.4) 90(7.7,3.8) 91(7.7,4.2) 92(7.7,4.6) 93(7.7,5) 94(7.7,5.4) 95(7.7,5.8) 96(7.7,6.2)
  oval 0.2x1.4 smd: 33(-6.2,-7.7) 34(-5.8,-7.7) 35(-5.4,-7.7) 36(-5,-7.7) 37(-4.6,-7.7) 38(-4.2,-7.7) 39(-3.8,-7.7) 40(-3.4,-7.7) 41(-3,-7.7) 42(-2.6,-7.7) 43(-2.2,-7.7) 44(-1.8,-7.7) 45(-1.4,-7.7) 46(-1,-7.7) 47(-0.6,-7.7) 48(-0.2,-7.7) 49(0.2,-7.7) 50(0.6,-7.7) 51(1,-7.7) 52(1.4,-7.7) 53(1.8,-7.7) 54(2.2,-7.7) 55(2.6,-7.7) 56(3,-7.7) 57(3.4,-7.7) 58(3.8,-7.7) 59(4.2,-7.7) 60(4.6,-7.7) 61(5,-7.7) 62(5.4,-7.7) 63(5.8,-7.7) 64(6.2,-7.7) 97(6.2,7.7) 98(5.8,7.7) 99(5.4,7.7) 100(5,7.7) 101(4.6,7.7) 102(4.2,7.7) 103(3.8,7.7) 104(3.4,7.7) 105(3,7.7) 106(2.6,7.7) 107(2.2,7.7) 108(1.8,7.7) 109(1.4,7.7) 110(1,7.7) 111(0.6,7.7) 112(0.2,7.7) 113(-0.2,7.7) 114(-0.6,7.7) 115(-1,7.7) 116(-1.4,7.7) 117(-1.8,7.7) 118(-2.2,7.7) 119(-2.6,7.7) 120(-3,7.7) 121(-3.4,7.7) 122(-3.8,7.7) 123(-4.2,7.7) 124(-4.6,7.7) 125(-5,7.7) 126(-5.4,7.7) 127(-5.8,7.7) 128(-6.2,7.7)
  silkscreen extent -7.7,-6.3 6.3,6.99, body extent -8,-8 8,8, height 1.07
PW0016A_N [mm] "TSOP, 16-Leads, Body 5x4.4mm, Pitch 0.65mm, IPC Medium Density"
  oval 1.4x0.45 smd: 1(-2.95,2.275) 2(-2.95,1.625) 3(-2.95,0.975) 4(-2.95,0.325) 5(-2.95,-0.325) 6(-2.95,-0.975) 7(-2.95,-1.625) 8(-2.95,-2.275) 9(2.95,-2.275) 10(2.95,-1.625) 11(2.95,-0.975) 12(2.95,-0.325) 13(2.95,0.325) 14(2.95,0.975) 15(2.95,1.625) 16(2.95,2.275)
  silkscreen extent -3.5,-2.55 1.85,2.75, body extent -3.21,-2.5 3.21,2.5, height 1
PW0024A-MFG [mm]
  rrect22% 1.5x0.45 smd paste+0 mask+0: 1(-2.9,3.575) 2(-2.9,2.925) 3(-2.9,2.275) 4(-2.9,1.625) 5(-2.9,0.975) 6(-2.9,0.325) 7(-2.9,-0.325) 8(-2.9,-0.975) 9(-2.9,-1.625) 10(-2.9,-2.275) 11(-2.9,-2.925) 12(-2.9,-3.575) 13(2.9,-3.575) 14(2.9,-2.925) 15(2.9,-2.275) 16(2.9,-1.625) 17(2.9,-0.975) 18(2.9,-0.325) 19(2.9,0.325) 20(2.9,0.975) 21(2.9,1.625) 22(2.9,2.275) 23(2.9,2.925) 24(2.9,3.575)
  silkscreen extent -4.37,-3.95 1.78,3.95, body extent -3.2,-3.9 3.2,3.9, height 1.2
RAY0024B-MFG [mm]
  rrect40% 0.625x0.25 smd paste+0 mask+0: 1(-1.637,1.5) 7(-1.637,-1.5) 13(1.637,-1.5) 19(1.637,1.5)
  rrect40% 0.6x0.25 smd paste+0 mask+0: 2(-1.65,1) 3(-1.65,0.5) 4(-1.65,0) 5(-1.65,-0.5) 6(-1.65,-1) 14(1.65,-1) 15(1.65,-0.5) 16(1.65,0) 17(1.65,0.5) 18(1.65,1)
  rrect40% 0.25x0.6 smd paste+0 mask+0: 8(-1,-1.65) 9(-0.5,-1.65) 10(0,-1.65) 11(0.5,-1.65) 12(1,-1.65) 20(1,1.65) 21(0.5,1.65) 22(0,1.65) 23(-0.5,1.65) 24(-1,1.65)
  round 0.777 smd paste-25.4 mask+0: ""(0.037,-0.003)
  Top Layer region: -1.95,0.075 -1.943,0.1 -1.925,0.118 -1.9,0.125 -1.9,0.125 -1.4,0.125 -1.378,0.12 -1.361,0.106 -1.361,0.106 -1.344,0.092 -1.322,0.088 -1.322,0.088 -0.426,0.088 -0.406,0.091 -0.39,0.102 -0.379,0.118 -0.375,0.138 -0.376,0.138 -0.376,0.601 -0.369,0.626 -0.35,0.644 -0.325,0.651 -0.326,0.651 0.456,0.651 0.48,0.644 0.499,0.626 0.505,0.601 0.505,0.601 0.505,0.1 0.509,0.081 0.52,0.065 0.536,0.054 0.556,0.05 0.556,0.05 1.303,0.05 1.324,0.055 1.342,0.068 1.352,0.088 1.352,0.088 1.362,0.107 1.379,0.12 1.4,0.125 1.4,0.125 1.9,0.125 1.925,0.118 1.943,0.1 1.95,0.075 1.95,0.075 1.95,-0.075 1.943,-0.1 1.925,-0.118 1.9,-0.125 1.9,-0.125 0.556,-0.125 0.536,-0.129 0.52,-0.14 0.509,-0.156 0.506,-0.175 0.505,-0.175 0.505,-0.601 0.499,-0.626 0.48,-0.644 0.456,-0.651 0.456,-0.651 -0.326,-0.651 -0.35,-0.644 -0.369,-0.626 -0.375,-0.601 -0.375,-0.601 -0.376,-0.138 -0.379,-0.118 -0.39,-0.102 -0.406,-0.091 -0.425,-0.088 -0.426,-0.087 -1.322,-0.088 -1.344,-0.092 -1.361,-0.106 -1.361,-0.106 -1.378,-0.12 -1.4,-0.125 -1.4,-0.125 -1.9,-0.125 -1.925,-0.118 -1.943,-0.1 -1.95,-0.075 -1.95,-0.075
  silkscreen extent -2.56,1.55 -2.31,1.8, body extent -2.05,-2.05 2.05,2.05, height 0.25
RSV0016A [mm] "QFN, 16-Leads, Body 1.8x2.6mm, Pitch 0.4mm, TI Recommended"
  rect 0.7x0.2 smd: 1(-0.75,0.6)
  rect 0.6x0.2 smd: 2(-0.8,0.2) 3(-0.8,-0.2) 4(-0.8,-0.6) 9(0.8,-0.6) 10(0.8,-0.2) 11(0.8,0.2) 12(0.8,0.6)
  rect 0.2x0.6 smd: 5(-0.6,-1.2) 6(-0.2,-1.2) 7(0.2,-1.2) 8(0.6,-1.2) 13(0.6,1.2) 14(0.2,1.2) 15(-0.2,1.2) 16(-0.6,1.2)
  silkscreen extent -1.08,-1.33 1.08,1.45, body extent -0.92,-1.32 0.92,1.33, height 0.56
RUX0012A [mm] "VQFN-HR-12"
  rrect25% 1.05x0.4 smd: 1(-0.675,0.325) 2(-0.675,-0.375) 7(0.675,-0.375) 8(0.675,0.325)
  rrect40% 0.2x0.6 smd: 3(-0.75,-1.15) 4(-0.25,-1.15) 5(0.25,-1.15) 6(0.75,-1.15) 9(0.75,1.15) 10(0.25,1.15) 11(-0.25,1.15) 12(-0.75,1.15)
  silkscreen extent -1.15,-1.4 1.15,1.35, body extent -1.05,-1.3 1.05,1.3, height 1
Samtec_QSH-030-01-X-D-A [mm] "Receptacle, 0.5 mm, 30x2, TH"
  rect 2.27x0.279 smd: 1(-2.865,7.25) 2(2.865,7.25) 3(-2.865,6.75) 4(2.865,6.75) 5(-2.865,6.25) 6(2.865,6.25) 7(-2.865,5.75) 8(2.865,5.75) 9(-2.865,5.25) 10(2.865,5.25) 11(-2.865,4.75) 12(2.865,4.75) 13(-2.865,4.25) 14(2.865,4.25) 15(-2.865,3.75) 16(2.865,3.75) 17(-2.865,3.25) 18(2.865,3.25) 19(-2.865,2.75) 20(2.865,2.75) 21(-2.865,2.25) 22(2.865,2.25) 23(-2.865,1.75) 24(2.865,1.75) 25(-2.865,1.25) 26(2.865,1.25) 27(-2.865,0.75) 28(2.865,0.75) 29(-2.865,0.25) 30(2.865,0.25) 31(-2.865,-0.25) 32(2.865,-0.25) 33(-2.865,-0.75) 34(2.865,-0.75) 35(-2.865,-1.25) 36(2.865,-1.25) 37(-2.865,-1.75) 38(2.865,-1.75) 39(-2.865,-2.25) 40(2.865,-2.25) 41(-2.865,-2.75) 42(2.865,-2.75) 43(-2.865,-3.25) 44(2.865,-3.25) 45(-2.865,-3.75) 46(2.865,-3.75) 47(-2.865,-4.25) 48(2.865,-4.25) 49(-2.865,-4.75) 50(2.865,-4.75) 51(-2.865,-5.25) 52(2.865,-5.25) 53(-2.865,-5.75) 54(2.865,-5.75) 55(-2.865,-6.25) 56(2.865,-6.25) 57(-2.865,-6.75) 58(2.865,-6.75) 59(-2.865,-7.25) 60(2.865,-7.25)
  round 0 hole 1.02 unplated: MH1(2.67,10.065) MH2(2.67,-10.065)
  rect 0.43x2.54 smd: MP1(0,8.065) MP4(0,-8.065)
  rect 0.43x4.7 smd: MP2(0,3.175) MP3(0,-3.175)
  silkscreen extent -3.85,-10.66 3.62,10.66, body extent -3.75,-10.64 3.75,10.67, height 3.25
Samtec_SSM-110-x-DV [mm] "Receptacle, 2.54mm, 10x2, SMT"
  rrect10% 1.02x2.22 smd: 1(-11.43,2.825) 2(-11.43,-2.825) 3(-8.89,2.825) 4(-8.89,-2.825) 5(-6.35,2.825) 6(-6.35,-2.825) 7(-3.81,2.825) 8(-3.81,-2.825) 9(-1.27,2.825) 10(-1.27,-2.825) 11(1.27,2.825) 12(1.27,-2.825) 13(3.81,2.825) 14(3.81,-2.825) 15(6.35,2.825) 16(6.35,-2.825) 17(8.89,2.825) 18(8.89,-2.825) 19(11.43,2.825) 20(11.43,-2.825)
  silkscreen extent -13.02,-2.54 12.7,2.54, body extent -12.7,-3.52 12.7,3.52, height 7.42
SM_RADIAL_6.3BMM [mm] "Nichicon 6.3x7.7"
  rect 3.5x1.6 smd: 1(-2.7,0) 2(2.7,0)
  silkscreen extent -3.4,-3.4 3.4,3.4, body extent -3.4,-3.4 3.4,3.4, height 8
SOD-128 [mm] "SMD, 2-Leads, Body 4x2.7mm, Height 1.1mm"
  rect 1.4x2.1 smd paste-0.1: 1(-2.2,0) 2(2.2,0)
  silkscreen extent -3.45,-1.45 2.95,1.45, body extent -2.5,-1.35 2.5,1.35, height 1.11
SOD-882 [mm] "Skyworks"
  rrect42% 0.475x0.75 smd mask+0.05: 1(-0.412,0) 2(0.412,0)
  silkscreen extent -1.1,-0.35 -0.87,0.35, body extent -0.5,-0.3 0.5,0.3, height 0.5
SOIC-8 [mm] "duplicate of SO-8.  SOIC, 8-Leads, Body 5.0x4.0mm (max), Pitch 1.27mm, IPC Medium Density"
  rrect17% 1.45x0.6 smd: 1(-2.725,1.905) 2(-2.725,0.635) 3(-2.725,-0.635) 4(-2.725,-1.905) 5(2.725,-1.905) 6(2.725,-0.635) 7(2.725,0.635) 8(2.725,1.905)
  silkscreen extent -3.5,-2.5 0.9,2.5, body extent -3,-2.45 3,2.45, height 1.63
SolderJumper [mil] "Solder Jumper"
  round 30 smd paste-40: 1(-30,0) 2(30,0)
  Top Layer region: -2.5,-50 -24.19,-45.05 -41.59,-31.17 -51.25,-11.13 -51.25,11.13 -41.59,31.17 -24.19,45.05 -2.5,50 -2.5,50
  Top Layer region: 2.5,-50 24.19,-45.05 41.59,-31.17 51.25,-11.13 51.25,11.13 41.59,31.17 24.19,45.05 2.5,50 2.5,50
SOT-323 [mm] "Diodes Inc recommended land pattern.  2016-02-24"
  rrect21% 0.6x0.47 smd: 1(-0.95,0.65) 2(-0.95,-0.65) 3(0.95,0)
  silkscreen extent -1.14,-1.22 0.77,1.22, body extent -1.13,-1.13 1.12,1.12, height 1.13
Sullins_xxC07SAAN [mm] "Header, 2.54 mm, 7x1, TH"
  rect 1.55x1.55 hole 1.016: 1(-7.62,0)
  round 1.55 hole 1.016: 2(-5.08,0) 3(-2.54,0) 4(0,0) 5(2.54,0) 6(5.08,0) 7(7.62,0)
  silkscreen extent -8.89,-1.27 8.89,1.7, body extent -8.89,-1.27 8.89,1.27, height 8.38
SW_218-2LP [mm] "SMD, 4-Leads, Body 3.71x5.8mm, Pitch 1.27mm"
  rect 1.27x0.76 smd: 1(-3.81,0.635) 2(-3.81,-0.635) 3(3.81,-0.635) 4(3.81,0.635)
  silkscreen extent -2.9,-1.86 2.9,2.09, body extent -4.22,-1.86 4.22,1.85, height 2.62
SW_218-6LPST [mm] "SMD, 12-Leads, Body 5.8x8.79mm"
  rect 1.27x0.76 smd: 1(-3.81,3.175) 2(-3.81,1.905) 3(-3.81,0.635) 4(-3.81,-0.635) 5(-3.81,-1.905) 6(-3.81,-3.175) 7(3.81,-3.175) 7(3.81,-3.175) 8(3.81,-1.905) 9(3.81,-0.635) 10(3.81,0.635) 11(3.81,1.905) 12(3.81,3.175)
  silkscreen extent -2.9,-4.4 2.9,4.7, body extent -4.22,-4.4 4.22,4.39, height 2.62
SW_CL-SB-12A-01 [mm] "SMD, 3-Leads, Body 8.5x3.5mm, Pitch 2.5mm"
  rect 1.6x1.2 smd: 1(-1.4,2.5) 2(1.4,0) 3(-1.4,-2.5)
  round 0 hole 0.9 unplated: MH1(0,3.4) MH2(0,-3.4)
  silkscreen extent -2.71,-4.25 1.75,4.25, body extent -1.75,-4.25 1.75,4.25, height 5.5
SW_PTS645SM43SMT [mm] "SMD, 4-Leads, Body 6x6mm"
  rrect8% 1.55x1.3 smd: 1(-3.975,2.25) 2(3.975,2.25) 3(-3.975,-2.25) 4(3.975,-2.25)
  body extent -4.5,-3 4.5,3, height 4.3
TFM201610ALMA [mm] "TDK"
  rrect17% 0.6x1.6 smd: 1(-0.9,0) 2(0.9,0)
  body extent -1.1,-0.9 1.1,0.9, height 1
TP_25MIL-SMT [mil]
  round 25 smd mask-2.5: 1(0,0)
TP_VIA_060RND040 [mil] "TP_VIA_060RND040"
  round 60 hole 40: 1(0,0)
TSSOP-8 [mm] "TSSOP, 8-Leads, Body 3.1x4.5mm (max), Pitch 0.65mm, IPC Medium Density"
  rrect50% 1.7x0.35 smd: 1(-2.85,0.975) 2(-2.85,0.325) 3(-2.85,-0.325) 4(-2.85,-0.975) 5(2.85,-0.975) 6(2.85,-0.325) 7(2.85,0.325) 8(2.85,0.975)
  silkscreen extent -2.4,-1.55 1.6,1.75, body extent -3.2,-1.55 3.2,1.55, height 1.07
TSW-102-07-G-S [mm] "Samtec 100mil, 1x2, 230 mil above insulator"
  rrect50% 1.65x1.65 hole 1.016: 1(-1.27,0)
  round 1.65 hole 1.016: 2(1.27,0)
  silkscreen extent -3.17,-1.27 2.54,1.27, body extent -2.54,-1.27 2.54,1.27, height 8.38
WEEE_Minimum [mil] "WEEElie bin"
  silkscreen extent -95,-172 99,104
Wurth_61300311021 [mm] "Header, 2.54 mm, 3x1, R/A, TH"
  rect 1.6x1.6 hole 1.1: 1(-2.54,0)
  round 1.6 hole 1.1: 2(0,0) 3(2.54,0)
  silkscreen extent -4.25,-4.04 3.81,-1.5, body extent -3.81,-10.04 3.81,0.32, height 2.55
WURTH_61300311121 [mm] "Header, 2.54mm, 3x1, TH"
  rrect50% 1.65x1.65 hole 1.15: 1(-2.54,0)
  round 1.65 hole 1.15: 2(0,0) 3(2.54,0)
  body extent -3.81,-1.27 3.81,1.27, height 8.54
Wurth_61300411021 [mm] "Header, 2.54 mm, 4x1, R/A, TH"
  rect 1.6x1.6 hole 1.1: 1(-3.81,0)
  round 1.6 hole 1.1: 2(-1.27,0) 3(1.27,0) 4(3.81,0)
  silkscreen extent -5.5,-4.04 5.08,-1.5, body extent -5.08,-10.04 5.08,0.32, height 2.55

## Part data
C1 C2 C4 C5 C7 C8 C10 C11 C12 C14 C16 C21 C25 C26 C45 C85 C121 C134: library part CMP-0078265-1, "CAP, CERM, 0.22 µF, 16 V,+/- 10%, X7R, AEC-Q200 Grade 1, 0402", Cap_Case=0402, Manufacturer=MuRata, Supplier Part Number 1=490-10671-1-ND, TempCo=X7R, Tolerance_%=10%, Value2=16V, ValueDisplayed=0.22µF
C3 C20 C27 C75 C76 C77 C78 C83 C117 C155 C156: library part CMP-0089543-1, "10µF ±10% 10V Ceramic Capacitor X7S 0805 (2012 Metric)", Digikey Part Number=445-173805-1-ND, Manufacturer=TDK, Mouser Part Number=810-CG4J3X7S1A106KAE, Operating Temperature Range="-55°C to +125°C", TempCo=22%, Temperature Characteristic=X7S, Tolerance_%=10%, ValueDisplayed=10uF
C6: library part CMP-0006330-2, "CAP, CERM, 0.047 uF, 50 V, +/- 10%, X7R, AEC-Q200 Grade 1, 0402", Cap_Case=0402, Manufacturer=TDK, Supplier Part Number 1=445-6897-1-ND, TempCo=X7R, Tolerance_%=10%, Value1="0.06407 ohm", Value2=50V, ValueDisplayed=0.047uF
C9 C24 C44: library part CMP-0048366-1, "22 µF ±20% 2.5V Ceramic Capacitor X7T 0603 (1608 Metric)", Digikey Part Number=490-GCM188D70E226ME36DCT-ND, Manufacturer=Murata, Mouser Part Number=81-GCM188D70E226M36D, Operating Temperature Range="-55°C to +125°C", TempCo=+22/-33%, Temperature Characteristic=X7T, Tolerance_%=20%, ValueDisplayed=22uF
C13 C15 C19: library part CMP-0086534-1, "Chip Multilayer Ceramic Capacitors for Automotive", Manufacturer=Murata, TempCo=-33+22%, Tolerance_%=20%
C17 C42 C79 C87 C105 C112 C124: library part CMP-0094968-1, "Multi-Layer Ceramic Capacitor 2.2uF 10V X7S ±10% 0402 Paper T/R", Manufacturer=Murata, Operating Temperature Range="-55°C to +125°C", TempCo=22%, Temperature Characteristic=X7S, Tolerance_%=10%, ValueDisplayed=2.2uF
C18 C22: library part CMP-0088425-1, "1µF ±10% 6.3V Ceramic Capacitor X7R 0402 (1005 Metric)", Digikey Part Number=490-18216-1-ND, Manufacturer=Murata, Mouser Part Number=81-GRT155R70J105KE1D, Operating Temperature Range="-55°C to +125°C", TempCo=15%, Temperature Characteristic=X7R, Tolerance_%=10%, ValueDisplayed=1uF
C30: library part CMP-0012608-3, "CAP, Polymer Hybrid, 68 uF, 35 V, +/- 20%, 35 ohm, 6.3x7.7 SMD", Manufacturer=Panasonic, Supplier Part Number 1=P15474CT-ND, Tolerance_%=20%, Value1="35 ohm", Value2=35V, ValueDisplayed=68uF
C31 C34 C36 C37 C38 C40 C41 C48 C52 C53 C56 C57 C58 C59 C60 C61 C63 C65 C67 C69 C94 C95 C99 C104 C106 C107 C109 C110 C113 C116 C123 C125 C126 C133 C135 C136 C138 C140 C142 C143 C144 C146 C150 C152 C153 C154 C158: library part CMP-0006356-2, "CAP, CERM, 0.1 uF, 50 V, +/- 10%, X7R, AEC-Q200 Grade 1, 0402", Cap_Case=0402, Manufacturer=MuRata, Supplier Part Number 1=490-10672-1-ND, TempCo=X7R, Tolerance_%=10%, Value1=Unknown, Value2=50V, ValueDisplayed=0.1uF
C32 C33: library part CMP-0006367-2, "CAP, CERM, 4.7 pF, 50 V, +/- 2%, C0G/NP0, 0402", Cap_Case=0402, Manufacturer=MuRata, Supplier Part Number 1=490-8102-1-ND, TempCo=C0G/NP0, Tolerance_%=2%, Value1=Unknown, Value2=50V, ValueDisplayed=4.7pF
C35 C54 C62 C73 C88 C100 C149 C151: library part CMP-0086540-3, "CAP, 1uF, 25V, ±10%, X7R, 0603", Manufacturer=Samsung, TempCo=15%, Tolerance_%=10%
C39 C111: library part CMP-0006361-2, "CAP, CERM, 4700 pF, 50 V, +/- 10%, X7R, AEC-Q200 Grade 1, 0402", Cap_Case=0402, Manufacturer=MuRata, Supplier Part Number 1=490-4915-1-ND, TempCo=X7R, Tolerance_%=10%, Value1=Unknown, Value2=50V, ValueDisplayed=4700pF
C43 C49 C50 C74 C137: library part CMP-0008702-2, "CAP, CERM, 4.7 uF, 50 V, +/- 10%, X7R, 1206", Cap_Case=1206_180, Manufacturer=TDK, Supplier Part Number 1=445-8032-1-ND, TempCo=X7R, Tolerance_%=10%, Value1="0.003158 ohm", Value2=50V, ValueDisplayed=4.7uF
C46 C47: library part CMP-0006564-3, "CAP, CERM, 10 uF, 10 V, +/- 20%, X5R, 0402", Cap_Case=0402, Manufacturer=MuRata, TempCo=X5R, Tolerance_%=20%, Value1=Unknown, Value2=10V, ValueDisplayed=10uF
C51 C66 C68 C93 C108 C114 C127: library part CMP-0006349-2, "CAP, CERM, 1 uF, 10 V, +/- 10%, X7S, AEC-Q200 Grade 1, 0402", Cap_Case=0402, Manufacturer=MuRata, Supplier Part Number 1=81-GCM155C71A105KE8D, TempCo=X7S, Tolerance_%=10%, Value1=Unknown, Value2=10V, ValueDisplayed=1uF
C55: library part CMP-0008944-2, "CAP, CERM, 47 uF, 10 V, +/- 10%, X5R, 1206", Cap_Case=1206, Manufacturer=MuRata, Supplier Part Number 1=81-GRM31CR61A476KE5L, TempCo=X5R, Tolerance_%=10%, Value1=Unknown, Value2=10V, ValueDisplayed=47uF
C64: library part CMP-0081062-1, "CAP, CERM, 10 µF, 25 V,+/- 5%, X7R, AEC-Q200 Grade 1, 1206", Cap_Case=1206_180, Manufacturer=Kemet, Supplier Part Number 1=399-15734-1-ND, TempCo=X7R, Tolerance_%=5%, Value2=25V, ValueDisplayed=10µF
C70 C71 C80 C81 C89 C90 C91: library part CMP-0092150-1, "Chip Multilayer Ceramic Capacitors for General Purpose, 1206, 22uF, X7R, 15%, 20%, 6.3V", Manufacturer=Murata, Operating Temperature Range="-55°C to +125°C", TempCo=15%, Temperature Characteristic=X7R, Tolerance_%=20%, ValueDisplayed=22uF
C72 C82 C103: library part CMP-0008940-2, "CAP, CERM, 47 uF, 6.3 V, +/- 20%, X5R, 1206", Cap_Case=1206, Manufacturer=MuRata, Supplier Part Number 1=490-3907-1-ND, TempCo=X5R, Tolerance_%=20%, Value1="0.003 ohm", Value2=6.3V, ValueDisplayed=47uF
C84 C92 C119 C120: library part CMP-0064967-2, "CAP, CERM, 0.47 uF, 10 V,+/- 10%, X7S, 0402", Cap_Case=0402, Manufacturer=MuRata, Supplier Part Number 1=490-14427-1-ND, TempCo=X7S, Tolerance_%=10%, Value1=Unknown, Value2=10V, ValueDisplayed=0.47uF
C86 C96 C157: library part CMP-0007497-5, "CAP, CERM, 10 uF, 10 V, +/- 10%, X5R, 0603", Cap_Case=0603, Manufacturer=MuRata, Supplier Part Number 1=81-GRM188Z71A106MA3D, TempCo=X7R, Tolerance_%=20%, Value1=Unknown, Value2=10V, ValueDisplayed=10uF
C97 C98: library part CMP-0860185-1, "CAP, CERM, 8 pF, 50 V,+/- 6.25%, C0G/NP0, 0402", Cap_Case=0402, Manufacturer=Yageo, TempCo=C0G/NP0, Tolerance_%=6.25%, Value2=50V, ValueDisplayed=8pF
C102 C115 C118 C128 C130: library part CMP-0006352-2, "CAP, CERM, 0.01 uF, 25 V, +/- 10%, X7R, 0402", Cap_Case=0402, Manufacturer=MuRata, Supplier Part Number 1=490-6043-2-ND, TempCo=X7R, Tolerance_%=10%, Value1=Unknown, Value2=25V, ValueDisplayed=0.01uF
C131: library part CMP-0094778-1, "Multilayer Ceramic Capacitors MLCC - SMD/SMT 0805 4.7uF 10%, 16VDC,  X7R 15%", Manufacturer=Murata, Operating Temperature Range="-55°C to +125°C", TempCo=15%, Temperature Characteristic=X7R, Tolerance_%=10%, ValueDisplayed=4.7uF
C132: library part CMP-0006218-2, "CAP, CERM, 220 pF, 50 V, +/- 5%, C0G/NP0, 0402", Cap_Case=0402, Manufacturer="Wurth Elektronik", Supplier Part Number 1=732-7477-1-ND, TempCo=C0G/NP0, Tolerance_%=5%, Value1=Unknown, Value2=50V, ValueDisplayed=220pF
C139 C141 C145: library part CMP-0007058-4, "CAP, CERM, 4.7 uF, 10 V, +/- 10%, X7S, 0603", Cap_Case=0603, Manufacturer=TDK, Supplier Part Number 1=445-14258-1-ND, TempCo=X7S, Tolerance_%=10%, Value1=Unknown, Value2=10V, ValueDisplayed=4.7uF
C147 C148: library part CMP-0087060-3, "Cap Ceramic 8pF 50V C0G 0.5pF SMD 0402 125C Paper T/R", Manufacturer="Murata Electronics North America", TempCo=30ppm/°C
"CAUTION HOT SURFACE1": library part CMP-0074837-2, "IEC 61010-1 Hot Surface Warning", Manufacturer="Texas Instruments"
D1 D8 D12: library part CMP-0078758-2, "Diode, Schottky, 30 V, 2 A, AEC-Q101, SOD-128", Manufacturer=Nexperia, Value1=2A, Value2=0.36V
D2: library part CMP-0077017-3, "Diode, Schottky, 30 V, 5 A, SOD-128", Manufacturer=Nexperia, Value1=5A, Value2=0.36V
D3 D5 D6 D7 D9 D10 D11 D13: library part CMP-0121062-1, "Yellow 589nm LED Indication - Discrete 2.1V 0603 (1608 Metric)", Color=Yellow, Digikey Part Number=751-TLMY1100-GS15CT-ND, Forward Current=20mA, Manufacturer=Vishay, Mouser Part Number=78-TLMY1100-GS15, Operating Temperature Range="-40°C to +100°C", Power_TotalModule=90mW
D4: library part CMP-0078187-3, "Diode, Schottky,  V, 0.01 A, SOD-882", Manufacturer="Skyworks Solutions", Value1=0.01A, Value2=0.34V
FB1 FB2 FB3: library part CMP-0091544-1, "30 Ohms @ 100MHz 1 Power Line Ferrite Bead 0805 (2012 Metric) 6A 10mOhm", Digikey Part Number=445-172906-1-ND, Impedance At Frequency="30Ω @ 100MHz", Manufacturer=TDK, Mouser Part Number=810-MPZ2012S300ATD25, Operating Temperature Range="-55°C to +125°C", Test Frequency=100MHz
FID5 FID6 FID7 FID8 FID9 FID10 FID11 FID12 FID13 FID14 FID15 FID16 FID17 FID18: library part CMP-0077181-1, "Fiducial mark.  There is nothing to buy or mount.", Manufacturer=N/A
J1 J3 J8: library part CMP-0054795-1, "Header, 2.54 mm, 3x1, Gold, R/A, TH", Color=Black, Manufacturer="Wurth Elektronik", Supplier Part Number 1=732-5336-ND
J2: library part CMP-0054584-1, "Header, 2.54 mm, 7x1, Gold, TH", Color=Black, Current_A=3A, Manufacturer="Sullins Connector Solutions", Supplier Part Number 1=S1011E-07-ND, Voltage_V=1.8kV
J4: library part CMP-0054797-1, "Header, 2.54 mm, 4x1, Gold, R/A, TH", Color=Black, Manufacturer="Wurth Elektronik", Supplier Part Number 1=732-5337-ND
J5 J10: library part CMP-0055293-1, "Connector, Receptacle, Micro-USB Type B, R/A, Bottom Mount SMT", Manufacturer=Molex, Supplier Part Number 1=WM1399CT-ND
J6: library part CMP-0075524-1, "Receptacle, 0.5 mm, 30x2, Gold, TH", Color=Black, Manufacturer=Samtec, Supplier Part Number 1=SAM8180-ND
J7: library part CMP-0079472-1, "DC POWER JACK, R/A, TH", Color=Black, Current_A=8A, Manufacturer="CUI Inc.", Supplier Part Number 1=CP-063AH-ND, Voltage_V=24V
J9 J13: library part CMP-0054796-4, "Header, 2.54 mm, 3x1, Gold, TH", Manufacturer="Wurth Elektronik", Supplier Part Number 1=732-5316-ND
J11 J12: library part CMP-0078182-1, "Receptacle, 2.54mm, 10x2, Gold with Tin tail, SMT", Color=Black, Current_A=5.2A, Manufacturer=Samtec, Supplier Part Number 1=SAM1150-10-ND, Voltage_V=405V
J14: library part CMP-0120118-1, Current_A=4A, Digikey Part Number=WM50015-07-ND, Manufacturer=Molex, Mouser Part Number=538-22-28-8072, Operating Temperature Range="-40°C to +80°C", Voltage_V=600V
J15: library part CMP-0080367-2, "Solder Jumper, SMT", Manufacturer=NA
L1: library part CMP-0094298-1, "Shielded Power Inductor 4.7uH 16mOhms 9.7A", Digikey Part Number=2457-XGL5050-472MEC-ND, Manufacturer=Coilcraft, Operating Temperature Range=to, Self Resonant Frequency=25MHz, Test Frequency=1MHz, Tolerance_%=20%
L2 L3 L7: library part CMP-0081523-1, "Ferrite Bead, 600 ohm @ 100 MHz, 0.3 A, 0402", Manufacturer=MuRata, Supplier Part Number 1=490-3998-1-ND, Value1="0.7 ohm", Value2=0.3A, ValueDisplayed="600 ohm"
L4: library part CMP-0095018-1, "100nH Shielded Multilayer Inductor 4A 19mOhm Max 0806 (2016 Metric)", Digikey Part Number=490-LQM2MPZR10MJHLCT-ND, Manufacturer=Murata, Mouser Part Number=81-LQM2MPZR10MJHL, Operating Temperature Range="-55°C to +125°C", Self Resonant Frequency=200MHz, Test Frequency=1MHz, Tolerance_%=20%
